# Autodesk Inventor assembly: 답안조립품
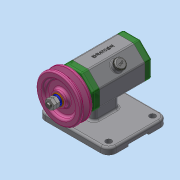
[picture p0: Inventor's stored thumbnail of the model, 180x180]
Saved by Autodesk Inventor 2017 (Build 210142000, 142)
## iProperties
Part Number: 답안조립품
Material: 일반
Document SubType Name: Assembly
Designer: MRC
Author: MRC
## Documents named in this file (16)
- C:\Users\MRC\Desktop\721006V1011\답안조립품.iam
- C:\Users\MRC\Desktop\721006V1011\본체.ipt
- C:\Users\MRC\Desktop\721006V1011\축.ipt
- C:\Users\MRC\Desktop\721006V1011\베어링 6002.ipt
- C:\Users\MRC\Desktop\721006V1011\오일 실 15x25x7.ipt
- C:\Users\MRC\Desktop\721006V1011\앞커버.ipt
- C:\Users\MRC\Desktop\721006V1011\키 3x3x12.ipt
- 키 3x3x12.ipt
- C:\Users\MRC\Desktop\721006V1011\볼트 M4x12.ipt
- C:\Users\MRC\Desktop\721006V1011\뒤커버.ipt
- C:\Users\MRC\Desktop\721006V1011\V벨트풀리.ipt
- C:\Users\MRC\Desktop\721006V1011\와셔 8x17.ipt
- C:\Users\MRC\Desktop\721006V1011\스프링와셔 8.ipt
- C:\Users\MRC\Desktop\721006V1011\너트 M8.ipt
- 너트 M8.ipt
- C:\Users\MRC\Desktop\721006V1011\고무캡.ipt
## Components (2 placed, 2 different names)
1. V벨트풀리:1
2. 고무캡:1
